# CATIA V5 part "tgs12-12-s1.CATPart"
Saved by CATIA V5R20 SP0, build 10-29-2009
Part number: TGS12-12-S1
Revision: 1
Definition: design
Nomenclature: TGS12-12-S1
Source: made
Description: NOT SPECIFIED
Bounding box of the stored display mesh (mm): x -22 to 0.8, y 0 to 12, z -5 to 5
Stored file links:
  C:\Users\Raffaele\Desktop\3D X SITO CF\I-MOLD\TGS-S1\tgs12-s1.step\tgs12-12-s1.CATPart
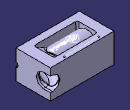
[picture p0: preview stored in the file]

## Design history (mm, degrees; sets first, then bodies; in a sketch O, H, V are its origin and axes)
Set1
  Line1 "LINE #3990": stored without definition
  DatumCurve1 "COMPOSITE_CURVE #4045"
  DatumCurve2 "COMPOSITE_CURVE #4094"
  DatumCurve3 "COMPOSITE_CURVE #4173"
  DatumCurve4 "COMPOSITE_CURVE #4216"
  DatumCurve5 "COMPOSITE_CURVE #4445"
  DatumCurve6 "COMPOSITE_CURVE #4586"
  DatumCurve7 "COMPOSITE_CURVE #4613"
  DatumCurve8 "COMPOSITE_CURVE #4671"
  DatumCurve9 "COMPOSITE_CURVE #4728"
  DatumCurve10 "COMPOSITE_CURVE #4757"
  DatumSurface1 "OPEN_SHELL #3980"
Body1 "MANIFOLD_SOLID_BREP #3981" (main body)
  Solid1: solid without history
